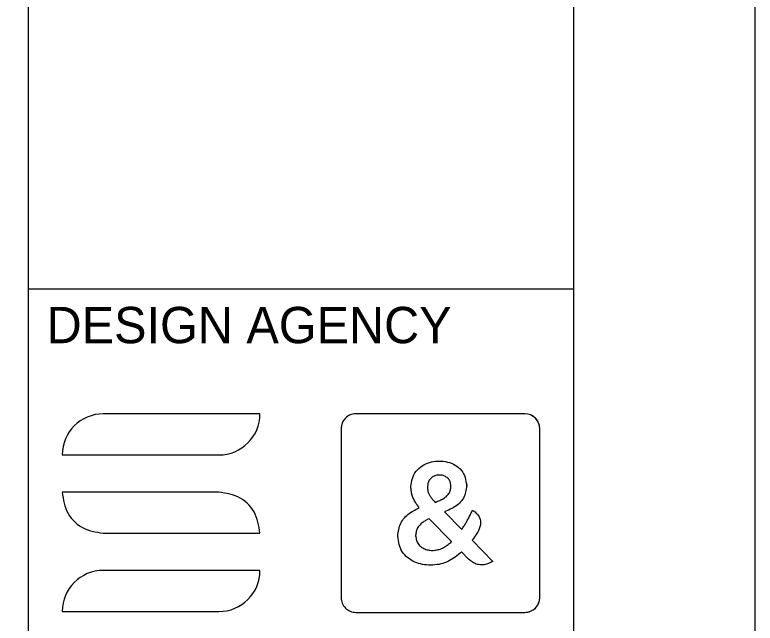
# Model space of a CAD drawing. Extents: x 0 to 34, y 0 to 30.1.
# Drawn here: x 31.963 to 34, y 4.079 to 5.754 of the extents above; entities that cross this region are included whole.
import ezdxf

# ---------------------------------------------------------------- set-up
doc = ezdxf.new("R2010")
doc.units = 0
for name, color, linetype in [('G-BRDR_LOGO', 7, 'Continuous'), ('SH_Border', 7, 'Continuous'), ('SH_Cut_Line', 7, 'Continuous'), ('SH_Data', 7, 'Continuous')]:
    doc.layers.add(name, color=color, linetype=linetype)

msp = doc.modelspace()

# ---------------------------------------------------------------- linework, layer by layer
at = {"layer": 'G-BRDR_LOGO'}
for p, q in [((33.3657, 4.6556), (32.9014, 4.6556)), ((32.8604, 4.6147), (32.8604, 4.1499)), ((33.4071, 4.1505), (33.4071, 4.6147)), ((33.1141, 4.483), (33.112, 4.4817)), ((33.1164, 4.4841), (33.1141, 4.483)), ((33.1187, 4.485), (33.1164, 4.4841)), ((33.1211, 4.4858), (33.1187, 4.485)), ((33.1235, 4.4863), (33.1211, 4.4858)), ((33.126, 4.4867), (33.1235, 4.4863)), ((33.1285, 4.487), (33.126, 4.4867)), ((33.131, 4.487), (33.1285, 4.487)), ((33.1335, 4.487), (33.131, 4.487)), ((33.136, 4.4867), (33.1335, 4.487)), ((33.1385, 4.4863), (33.136, 4.4867)), ((33.1409, 4.4857), (33.1385, 4.4863)), ((33.1433, 4.485), (33.1409, 4.4857)), ((33.1456, 4.484), (33.1433, 4.485)), ((33.1478, 4.4829), (33.1456, 4.484)), ((33.15, 4.4816), (33.1478, 4.4829)), ((33.0996, 4.4636), (33.0991, 4.4612)), ((33.1003, 4.466), (33.0996, 4.4636)), ((33.101, 4.4684), (33.1003, 4.466)), ((33.102, 4.4706), (33.101, 4.4684)), ((33.1032, 4.4728), (33.102, 4.4706)), ((33.1046, 4.4748), (33.1032, 4.4728)), ((33.1062, 4.4768), (33.1046, 4.4748)), ((33.108, 4.4785), (33.1062, 4.4768)), ((33.1099, 4.4802), (33.108, 4.4785)), ((33.112, 4.4817), (33.1099, 4.4802)), ((33.152, 4.48), (33.15, 4.4816)), ((33.1539, 4.4784), (33.152, 4.48)), ((33.1556, 4.4765), (33.1539, 4.4784)), ((33.1571, 4.4746), (33.1556, 4.4765)), ((33.1585, 4.4725), (33.1571, 4.4746)), ((33.1595, 4.4703), (33.1585, 4.4725)), ((33.1604, 4.468), (33.1595, 4.4703)), ((33.1611, 4.4656), (33.1604, 4.468)), ((33.1616, 4.4632), (33.1611, 4.4656)), ((33.1621, 4.4607), (33.1616, 4.4632)), ((33.0984, 4.4562), (33.0981, 4.4537)), ((33.0981, 4.4537), (33.0981, 4.4529)), ((33.0981, 4.4529), (33.0983, 4.4508)), ((33.0983, 4.4508), (33.0985, 4.4488)), ((33.0987, 4.4587), (33.0984, 4.4562)), ((33.0985, 4.4488), (33.0987, 4.4467)), ((33.0991, 4.4612), (33.0987, 4.4587)), ((33.0987, 4.4467), (33.099, 4.4447)), ((33.099, 4.4447), (33.0994, 4.4427)), ((33.0994, 4.4427), (33.0999, 4.4407)), ((33.1595, 4.4409), (33.1604, 4.4436)), ((33.1604, 4.4436), (33.1611, 4.4463)), ((33.1611, 4.4463), (33.1617, 4.4492)), ((33.1617, 4.4492), (33.1623, 4.452)), ((33.1624, 4.4582), (33.1621, 4.4607)), ((33.1623, 4.452), (33.1627, 4.4549)), ((33.1627, 4.4557), (33.1624, 4.4582)), ((33.1627, 4.4549), (33.1627, 4.4557)), ((33.0999, 4.4407), (33.1005, 4.4387)), ((33.1005, 4.4387), (33.1012, 4.4368)), ((33.1012, 4.4368), (33.102, 4.4349)), ((33.102, 4.4349), (33.1029, 4.4331)), ((33.1029, 4.4331), (33.104, 4.4312)), ((33.104, 4.4312), (33.105, 4.4295)), ((33.105, 4.4295), (33.1062, 4.4277)), ((33.1062, 4.4277), (33.1074, 4.426)), ((33.1074, 4.426), (33.1086, 4.4243)), ((33.1086, 4.4243), (33.1098, 4.4227)), ((33.1098, 4.4227), (33.1111, 4.4211)), ((33.1398, 4.421), (33.1422, 4.4225)), ((33.1422, 4.4225), (33.1447, 4.4241)), ((33.1447, 4.4241), (33.1471, 4.4257)), ((33.1471, 4.4257), (33.1494, 4.4275)), ((33.1494, 4.4275), (33.1516, 4.4294)), ((33.1516, 4.4294), (33.1536, 4.4315)), ((33.1536, 4.4315), (33.1554, 4.4336)), ((33.1554, 4.4336), (33.157, 4.4359)), ((33.157, 4.4359), (33.1584, 4.4384)), ((33.1584, 4.4384), (33.1595, 4.4409)), ((33.1111, 4.4211), (33.1124, 4.4195)), ((33.1124, 4.4195), (33.1137, 4.4179)), ((33.1137, 4.4179), (33.1164, 4.4148)), ((33.1164, 4.4148), (33.1191, 4.4117)), ((33.1191, 4.4117), (33.1243, 4.4138)), ((33.1243, 4.4138), (33.127, 4.4149)), ((33.127, 4.4149), (33.1296, 4.416)), ((33.1296, 4.416), (33.1321, 4.4172)), ((33.1321, 4.4172), (33.1347, 4.4184)), ((33.1347, 4.4184), (33.1372, 4.4197)), ((33.1372, 4.4197), (33.1398, 4.421)), ((33.0905, 4.3604), (33.0882, 4.3589)), ((33.0929, 4.3617), (33.0905, 4.3604)), ((33.0952, 4.363), (33.0929, 4.3617)), ((33.0976, 4.3643), (33.0952, 4.363)), ((33.1, 4.3656), (33.0976, 4.3643)), ((33.1024, 4.3668), (33.1, 4.3656)), ((33.1643, 4.3037), (33.1024, 4.3668)), ((33.0711, 4.3416), (33.0698, 4.3392)), ((33.0725, 4.344), (33.0711, 4.3416)), ((33.0741, 4.3462), (33.0725, 4.344)), ((33.0758, 4.3483), (33.0741, 4.3462)), ((33.0776, 4.3504), (33.0758, 4.3483)), ((33.0796, 4.3523), (33.0776, 4.3504)), ((33.0816, 4.3541), (33.0796, 4.3523)), ((33.0838, 4.3558), (33.0816, 4.3541)), ((33.086, 4.3574), (33.0838, 4.3558)), ((33.0882, 4.3589), (33.086, 4.3574)), ((33.0659, 4.3235), (33.0655, 4.3208)), ((33.0655, 4.3208), (33.0655, 4.32)), ((33.0655, 4.32), (33.0661, 4.3168)), ((33.0663, 4.3262), (33.0659, 4.3235)), ((33.0667, 4.3289), (33.0663, 4.3262)), ((33.0673, 4.3316), (33.0667, 4.3289)), ((33.068, 4.3342), (33.0673, 4.3316)), ((33.0688, 4.3367), (33.068, 4.3342)), ((33.0698, 4.3392), (33.0688, 4.3367)), ((33.0661, 4.3168), (33.0666, 4.3137)), ((33.0666, 4.3137), (33.0673, 4.3106)), ((33.0673, 4.3106), (33.068, 4.3076)), ((33.068, 4.3076), (33.069, 4.3047)), ((33.069, 4.3047), (33.0701, 4.3018)), ((33.0701, 4.3018), (33.0716, 4.2991)), ((33.0716, 4.2991), (33.0733, 4.2966)), ((33.1573, 4.2977), (33.1596, 4.2997)), ((33.1596, 4.2997), (33.162, 4.3017)), ((33.162, 4.3017), (33.1643, 4.3037)), ((33.0733, 4.2966), (33.0752, 4.2942)), ((33.0752, 4.2942), (33.0774, 4.292)), ((33.0774, 4.292), (33.0798, 4.2899)), ((33.0798, 4.2899), (33.0824, 4.288)), ((33.0824, 4.288), (33.0851, 4.2864)), ((33.0851, 4.2864), (33.0879, 4.2849)), ((33.0879, 4.2849), (33.0907, 4.2835)), ((33.0907, 4.2835), (33.0937, 4.2824)), ((33.0937, 4.2824), (33.0967, 4.2815)), ((33.0967, 4.2815), (33.0997, 4.2808)), ((33.0997, 4.2808), (33.1028, 4.2802)), ((33.1028, 4.2802), (33.1059, 4.2798)), ((33.1059, 4.2798), (33.109, 4.2796)), ((33.109, 4.2796), (33.1121, 4.2795)), ((33.1121, 4.2795), (33.1152, 4.2796)), ((33.1152, 4.2796), (33.1183, 4.2799)), ((33.1183, 4.2799), (33.1214, 4.2803)), ((33.1214, 4.2803), (33.1244, 4.2809)), ((33.1244, 4.2809), (33.1275, 4.2816)), ((33.1275, 4.2816), (33.1304, 4.2824)), ((33.1304, 4.2824), (33.1334, 4.2834)), ((33.1334, 4.2834), (33.1363, 4.2846)), ((33.1363, 4.2846), (33.1391, 4.2858)), ((33.1391, 4.2858), (33.1419, 4.2872)), ((33.1419, 4.2872), (33.1446, 4.2887)), ((33.1446, 4.2887), (33.1473, 4.2903)), ((33.1473, 4.2903), (33.1499, 4.292)), ((33.1499, 4.292), (33.1524, 4.2939)), ((33.1524, 4.2939), (33.1548, 4.2957)), ((33.1548, 4.2957), (33.1573, 4.2977)), ((32.9014, 4.109), (33.366, 4.109))]:
    msp.add_line(p, q, dxfattribs=at)
for points in [[(32.6372, 4.6556), (32.2061, 4.6556)], [(32.8786, 4.6487), (32.8778, 4.6482), (32.8755, 4.6466), (32.8734, 4.6447), (32.8714, 4.6427), (32.8695, 4.6406), (32.8679, 4.6383), (32.8674, 4.6375)], [(33.366, 4.6556), (32.9014, 4.6556)], [(33.4024, 4.6334), (33.4024, 4.6334), (33.4012, 4.6359), (33.3997, 4.6383), (33.398, 4.6406), (33.3962, 4.6427), (33.3942, 4.6447), (33.392, 4.6466), (33.3898, 4.6482), (33.3874, 4.6497), (33.3866, 4.65)], [(32.8604, 4.6147), (32.8604, 4.1499)], [(33.4071, 4.1499), (33.4071, 4.6147)], [(32.0929, 4.5424), (32.524, 4.5424)], [(33.0884, 4.5151), (33.0934, 4.5176), (33.0986, 4.5198), (33.1039, 4.5216), (33.1093, 4.523), (33.1148, 4.5242), (33.1203, 4.5249), (33.1259, 4.5254), (33.1315, 4.5255), (33.1371, 4.5254), (33.1426, 4.5249), (33.1482, 4.5241), (33.1536, 4.5229), (33.159, 4.5214), (33.1643, 4.5195), (33.1694, 4.5172), (33.1744, 4.5145), (33.1791, 4.5114), (33.1836, 4.5079), (33.1878, 4.5041), (33.1915, 4.4999), (33.1948, 4.4955), (33.1976, 4.4907), (33.1998, 4.4857), (33.2016, 4.4805), (33.203, 4.4752), (33.2041, 4.4697), (33.2051, 4.4641), (33.2061, 4.4581), (33.2054, 4.4532), (33.2048, 4.4488), (33.2041, 4.4444), (33.2032, 4.4401), (33.2021, 4.4358), (33.2008, 4.4317), (33.1992, 4.4277), (33.1973, 4.4238), (33.195, 4.4201), (33.1924, 4.4165), (33.1895, 4.4132), (33.1864, 4.41), (33.1831, 4.4069), (33.1797, 4.4041), (33.1761, 4.4015), (33.1724, 4.3991), (33.1686, 4.3968), (33.1648, 4.3947), (33.1609, 4.3927), (33.1569, 4.3908), (33.1529, 4.389), (33.1489, 4.3872), (33.1449, 4.3855), (33.1925, 4.3371), (33.194, 4.3393), (33.1954, 4.3415), (33.1968, 4.3438), (33.1983, 4.346), (33.1997, 4.3483), (33.2011, 4.3506), (33.2025, 4.3529), (33.2038, 4.3551), (33.2052, 4.3574), (33.2065, 4.3598), (33.2078, 4.3621), (33.2091, 4.3644), (33.2103, 4.3668), (33.2116, 4.3691), (33.2128, 4.3715), (33.214, 4.3739), (33.2152, 4.3763), (33.2164, 4.3786), (33.2176, 4.381), (33.2188, 4.3834), (33.2199, 4.3858), (33.2211, 4.3882), (33.2223, 4.3906), (33.2246, 4.3889), (33.2269, 4.3871), (33.2292, 4.3853), (33.2314, 4.3834), (33.2334, 4.3815), (33.2354, 4.3794), (33.2372, 4.3772), (33.2389, 4.3749), (33.2403, 4.3724), (33.2416, 4.3697), (33.2426, 4.367), (33.2434, 4.3642), (33.244, 4.3613), (33.2444, 4.3585), (33.2445, 4.3556), (33.2443, 4.3527), (33.2439, 4.3499), (33.2433, 4.3471), (33.2426, 4.3444), (33.2417, 4.3416), (33.2407, 4.3389), (33.2397, 4.3362), (33.2386, 4.3335), (33.2379, 4.3323), (33.2368, 4.3305), (33.2354, 4.3283), (33.234, 4.326), (33.2325, 4.3238), (33.2311, 4.3215), (33.2296, 4.3193), (33.2281, 4.317), (33.2266, 4.3149), (33.225, 4.3127), (33.2235, 4.3105), (33.2223, 4.3088), (33.2215, 4.3077), (33.278, 4.2493), (33.2751, 4.2478), (33.2723, 4.2464), (33.2694, 4.245), (33.2665, 4.2437), (33.2636, 4.2425), (33.2606, 4.2415), (33.2576, 4.2407), (33.2545, 4.2401), (33.2513, 4.2397), (33.2482, 4.2395), (33.2449, 4.2396), (33.2418, 4.2399), (33.2386, 4.2404), (33.2355, 4.2411), (33.2325, 4.2421), (33.2295, 4.2433), (33.2267, 4.2446), (33.224, 4.2462), (33.2213, 4.2479), (33.2187, 4.2497), (33.2161, 4.2515), (33.2136, 4.2535), (33.2111, 4.2554), (33.1921, 4.2752), (33.1878, 4.2716), (33.1835, 4.268), (33.1792, 4.2646), (33.1747, 4.2612), (33.1702, 4.258), (33.1655, 4.2551), (33.1606, 4.2523), (33.1556, 4.2498), (33.1505, 4.2476), (33.1453, 4.2456), (33.14, 4.2439), (33.1346, 4.2424), (33.1292, 4.2412), (33.1237, 4.2403), (33.1181, 4.2396), (33.1126, 4.2392), (33.107, 4.2391), (33.1014, 4.2392), (33.0958, 4.2395), (33.0903, 4.2401), (33.0848, 4.241), (33.0793, 4.2422), (33.0739, 4.2437), (33.0685, 4.2455), (33.0633, 4.2476), (33.0582, 4.2501), (33.0532, 4.2528), (33.0484, 4.2559), (33.0438, 4.2593), (33.0395, 4.263), (33.0355, 4.267), (33.0319, 4.2712), (33.0288, 4.2757), (33.0261, 4.2805), (33.0239, 4.2855), (33.0221, 4.2907), (33.0205, 4.296), (33.0193, 4.3015), (33.0182, 4.3071), (33.0172, 4.3127), (33.0163, 4.3187), (33.0169, 4.3238), (33.0174, 4.3283), (33.0181, 4.3328), (33.0189, 4.3372), (33.0199, 4.3416), (33.0211, 4.3459), (33.0226, 4.3501), (33.0244, 4.3542), (33.0265, 4.3582), (33.029, 4.362), (33.0317, 4.3657), (33.0346, 4.3692), (33.0377, 4.3725), (33.041, 4.3756), (33.0445, 4.3786), (33.0481, 4.3813), (33.0518, 4.3839), (33.0556, 4.3863), (33.0595, 4.3886), (33.0634, 4.3908), (33.0674, 4.3929), (33.0714, 4.3949), (33.0755, 4.397), (33.0738, 4.3992), (33.0722, 4.4014), (33.0706, 4.4037), (33.069, 4.406), (33.0675, 4.4082), (33.066, 4.4106), (33.0645, 4.4129), (33.0631, 4.4153), (33.0618, 4.4177), (33.0605, 4.4202), (33.0593, 4.4227), (33.0582, 4.4252), (33.0572, 4.4278), (33.0563, 4.4304), (33.0555, 4.4331), (33.0548, 4.4357), (33.0542, 4.4384), (33.0538, 4.4411), (33.0534, 4.4439), (33.0531, 4.4466), (33.0529, 4.4494), (33.0526, 4.4521), (33.0524, 4.4554), (33.0534, 4.4613), (33.0543, 4.4669), (33.0555, 4.4724), (33.0569, 4.4778), (33.0587, 4.483), (33.0608, 4.488), (33.0635, 4.4928), (33.0667, 4.4973), (33.0704, 4.5015), (33.0744, 4.5054), (33.0788, 4.509), (33.0835, 4.5122), (33.0884, 4.5151)], [(32.6168, 4.3923), (32.6122, 4.3986), (32.6072, 4.4045), (32.6017, 4.41), (32.5957, 4.4151), (32.5895, 4.4196), (32.5829, 4.4237), (32.5761, 4.4271), (32.569, 4.43), (32.5618, 4.4324), (32.5545, 4.4344), (32.547, 4.4361), (32.5394, 4.4375), (32.5317, 4.4388), (32.524, 4.44), (32.0929, 4.44), (32.0941, 4.4324), (32.0954, 4.4247), (32.0968, 4.4171), (32.0985, 4.4096), (32.1006, 4.4023), (32.103, 4.395), (32.1058, 4.388), (32.1093, 4.3812), (32.1133, 4.3746), (32.1179, 4.3684), (32.1229, 4.3624), (32.1284, 4.3569), (32.1344, 4.3518), (32.1406, 4.3473), (32.1472, 4.3433), (32.154, 4.3398), (32.1611, 4.3369), (32.1683, 4.3345), (32.1756, 4.3325), (32.1831, 4.3308), (32.1907, 4.3294), (32.1984, 4.3281), (32.2061, 4.3269), (32.6372, 4.3269), (32.636, 4.3345), (32.6347, 4.3422), (32.6333, 4.3498), (32.6316, 4.3573), (32.6296, 4.3646), (32.6271, 4.3719), (32.6243, 4.3789), (32.6208, 4.3857), (32.6168, 4.3923)], [(32.6372, 4.2245), (32.2061, 4.2245)], [(32.0929, 4.1113), (32.524, 4.1113)], [(32.9014, 4.109), (33.366, 4.109)]]:
    msp.add_lwpolyline(points, dxfattribs=at)
for points in [[(33.1921, 4.2752), (33.1878, 4.2716), (33.1835, 4.268), (33.1792, 4.2646), (33.1747, 4.2612), (33.1702, 4.258), (33.1655, 4.2551), (33.1606, 4.2523), (33.1556, 4.2498), (33.1505, 4.2476), (33.1453, 4.2456), (33.14, 4.2439), (33.1346, 4.2424), (33.1292, 4.2412), (33.1237, 4.2403), (33.1181, 4.2396), (33.1126, 4.2392), (33.107, 4.2391), (33.1014, 4.2392), (33.0958, 4.2395), (33.0903, 4.2401), (33.0848, 4.241), (33.0793, 4.2422), (33.0739, 4.2437), (33.0685, 4.2455), (33.0633, 4.2476), (33.0582, 4.2501), (33.0532, 4.2528), (33.0484, 4.2559), (33.0438, 4.2593), (33.0395, 4.263), (33.0355, 4.267), (33.0319, 4.2712), (33.0288, 4.2757), (33.0261, 4.2805), (33.0239, 4.2855), (33.0221, 4.2907), (33.0205, 4.296), (33.0193, 4.3015), (33.0182, 4.3071), (33.0172, 4.3127), (33.0163, 4.3184), (33.0163, 4.3192), (33.0169, 4.3238), (33.0174, 4.3283), (33.0181, 4.3328), (33.0189, 4.3372), (33.0199, 4.3416), (33.0211, 4.3459), (33.0226, 4.3501), (33.0244, 4.3542), (33.0265, 4.3582), (33.029, 4.362), (33.0317, 4.3657), (33.0346, 4.3692), (33.0377, 4.3725), (33.041, 4.3756), (33.0445, 4.3786), (33.0481, 4.3813), (33.0518, 4.3839), (33.0556, 4.3863), (33.0595, 4.3886), (33.0634, 4.3908), (33.0674, 4.3929), (33.0714, 4.3949), (33.0755, 4.397), (33.0738, 4.3992), (33.0722, 4.4014), (33.0706, 4.4037), (33.069, 4.406), (33.0675, 4.4082), (33.066, 4.4106), (33.0645, 4.4129), (33.0631, 4.4153), (33.0618, 4.4177), (33.0605, 4.4202), (33.0593, 4.4227), (33.0582, 4.4252), (33.0572, 4.4278), (33.0563, 4.4304), (33.0555, 4.4331), (33.0548, 4.4357), (33.0542, 4.4384), (33.0538, 4.4411), (33.0534, 4.4439), (33.0531, 4.4466), (33.0529, 4.4494), (33.0526, 4.4521), (33.0524, 4.4549), (33.0524, 4.4557), (33.0534, 4.4613), (33.0543, 4.4669), (33.0555, 4.4724), (33.0569, 4.4778), (33.0587, 4.483), (33.0608, 4.488), (33.0635, 4.4928), (33.0667, 4.4973), (33.0704, 4.5015), (33.0744, 4.5054), (33.0788, 4.509), (33.0835, 4.5122), (33.0884, 4.5151), (33.0934, 4.5176), (33.0986, 4.5198), (33.1039, 4.5216), (33.1093, 4.523), (33.1148, 4.5242), (33.1203, 4.5249), (33.1259, 4.5254), (33.1315, 4.5255), (33.1371, 4.5254), (33.1426, 4.5249), (33.1482, 4.5241), (33.1536, 4.5229), (33.159, 4.5214), (33.1643, 4.5195), (33.1694, 4.5172), (33.1744, 4.5145), (33.1791, 4.5114), (33.1836, 4.5079), (33.1878, 4.5041), (33.1915, 4.4999), (33.1948, 4.4955), (33.1976, 4.4907), (33.1998, 4.4857), (33.2016, 4.4805), (33.203, 4.4752), (33.2041, 4.4697), (33.2051, 4.4641), (33.206, 4.4585), (33.206, 4.4577), (33.2054, 4.4532), (33.2048, 4.4488), (33.2041, 4.4444), (33.2032, 4.4401), (33.2021, 4.4358), (33.2008, 4.4317), (33.1992, 4.4277), (33.1973, 4.4238), (33.195, 4.4201), (33.1924, 4.4165), (33.1895, 4.4132), (33.1864, 4.41), (33.1831, 4.4069), (33.1797, 4.4041), (33.1761, 4.4015), (33.1724, 4.3991), (33.1686, 4.3968), (33.1648, 4.3947), (33.1609, 4.3927), (33.1569, 4.3908), (33.1529, 4.389), (33.1489, 4.3872), (33.1449, 4.3855), (33.1925, 4.3371), (33.194, 4.3393), (33.1954, 4.3415), (33.1968, 4.3438), (33.1983, 4.346), (33.1997, 4.3483), (33.2011, 4.3506), (33.2025, 4.3529), (33.2038, 4.3551), (33.2052, 4.3574), (33.2065, 4.3598), (33.2078, 4.3621), (33.2091, 4.3644), (33.2103, 4.3668), (33.2116, 4.3691), (33.2128, 4.3715), (33.214, 4.3739), (33.2152, 4.3763), (33.2164, 4.3786), (33.2176, 4.381), (33.2188, 4.3834), (33.2199, 4.3858), (33.2211, 4.3882), (33.2223, 4.3906), (33.2246, 4.3889), (33.2269, 4.3871), (33.2292, 4.3853), (33.2314, 4.3834), (33.2334, 4.3815), (33.2354, 4.3794), (33.2372, 4.3772), (33.2389, 4.3749), (33.2403, 4.3724), (33.2416, 4.3697), (33.2426, 4.367), (33.2434, 4.3642), (33.244, 4.3613), (33.2444, 4.3585), (33.2445, 4.3556), (33.2443, 4.3527), (33.2439, 4.3499), (33.2433, 4.3471), (33.2426, 4.3444), (33.2417, 4.3416), (33.2407, 4.3389), (33.2397, 4.3362), (33.2386, 4.3335), (33.2379, 4.3323), (33.2372, 4.3312), (33.2365, 4.33), (33.2358, 4.3289), (33.2351, 4.3278), (33.2343, 4.3266), (33.2336, 4.3255), (33.2329, 4.3243), (33.2322, 4.3232), (33.2314, 4.3221), (33.2307, 4.321), (33.23, 4.3198), (33.2292, 4.3187), (33.2285, 4.3176), (33.2277, 4.3165), (33.2269, 4.3154), (33.2262, 4.3143), (33.2254, 4.3132), (33.2246, 4.3121), (33.2238, 4.311), (33.2231, 4.3099), (33.2223, 4.3088), (33.2215, 4.3077), (33.278, 4.2493), (33.2751, 4.2478), (33.2723, 4.2464), (33.2694, 4.245), (33.2665, 4.2437), (33.2636, 4.2425), (33.2606, 4.2415), (33.2576, 4.2407), (33.2545, 4.2401), (33.2513, 4.2397), (33.2482, 4.2395), (33.2449, 4.2396), (33.2418, 4.2399), (33.2386, 4.2404), (33.2355, 4.2411), (33.2325, 4.2421), (33.2295, 4.2433), (33.2267, 4.2446), (33.224, 4.2462), (33.2213, 4.2479), (33.2187, 4.2497), (33.2161, 4.2515), (33.2136, 4.2535), (33.2111, 4.2554)], [(33.1627, 4.4557), (33.1624, 4.4582), (33.1621, 4.4607), (33.1616, 4.4632), (33.1611, 4.4656), (33.1604, 4.468), (33.1595, 4.4703), (33.1585, 4.4725), (33.1571, 4.4746), (33.1556, 4.4765), (33.1539, 4.4784), (33.152, 4.48), (33.15, 4.4816), (33.1478, 4.4829), (33.1456, 4.484), (33.1433, 4.485), (33.1409, 4.4857), (33.1385, 4.4863), (33.136, 4.4867), (33.1335, 4.487), (33.131, 4.487), (33.1285, 4.487), (33.126, 4.4867), (33.1235, 4.4863), (33.1211, 4.4858), (33.1187, 4.485), (33.1164, 4.4841), (33.1141, 4.483), (33.112, 4.4817), (33.1099, 4.4802), (33.108, 4.4785), (33.1062, 4.4768), (33.1046, 4.4748), (33.1032, 4.4728), (33.102, 4.4706), (33.101, 4.4684), (33.1003, 4.466), (33.0996, 4.4636), (33.0991, 4.4612), (33.0987, 4.4587), (33.0984, 4.4562), (33.0981, 4.4537), (33.0981, 4.4529), (33.0983, 4.4508), (33.0985, 4.4488), (33.0987, 4.4467), (33.099, 4.4447), (33.0994, 4.4427), (33.0999, 4.4407), (33.1005, 4.4387), (33.1012, 4.4368), (33.102, 4.4349), (33.1029, 4.4331), (33.104, 4.4312), (33.105, 4.4295), (33.1062, 4.4277), (33.1074, 4.426), (33.1086, 4.4243), (33.1098, 4.4227), (33.1111, 4.4211), (33.1124, 4.4195), (33.1137, 4.4179), (33.1164, 4.4148), (33.1191, 4.4117), (33.1243, 4.4138), (33.127, 4.4149), (33.1296, 4.416), (33.1321, 4.4172), (33.1347, 4.4184), (33.1372, 4.4197), (33.1398, 4.421), (33.1422, 4.4225), (33.1447, 4.4241), (33.1471, 4.4257), (33.1494, 4.4275), (33.1516, 4.4294), (33.1536, 4.4315), (33.1554, 4.4336), (33.157, 4.4359), (33.1584, 4.4384), (33.1595, 4.4409), (33.1604, 4.4436), (33.1611, 4.4463), (33.1617, 4.4492), (33.1623, 4.452), (33.1627, 4.4549)], [(33.0655, 4.32), (33.0661, 4.3168), (33.0666, 4.3137), (33.0673, 4.3106), (33.068, 4.3076), (33.069, 4.3047), (33.0701, 4.3018), (33.0716, 4.2991), (33.0733, 4.2966), (33.0752, 4.2942), (33.0774, 4.292), (33.0798, 4.2899), (33.0824, 4.288), (33.0851, 4.2864), (33.0879, 4.2849), (33.0907, 4.2835), (33.0937, 4.2824), (33.0967, 4.2815), (33.0997, 4.2808), (33.1028, 4.2802), (33.1059, 4.2798), (33.109, 4.2796), (33.1121, 4.2795), (33.1152, 4.2796), (33.1183, 4.2799), (33.1214, 4.2803), (33.1244, 4.2809), (33.1275, 4.2816), (33.1304, 4.2824), (33.1334, 4.2834), (33.1363, 4.2846), (33.1391, 4.2858), (33.1419, 4.2872), (33.1446, 4.2887), (33.1473, 4.2903), (33.1499, 4.292), (33.1524, 4.2939), (33.1548, 4.2957), (33.1573, 4.2977), (33.1596, 4.2997), (33.162, 4.3017), (33.1643, 4.3037), (33.1024, 4.3668), (33.1, 4.3656), (33.0976, 4.3643), (33.0952, 4.363), (33.0929, 4.3617), (33.0905, 4.3604), (33.0882, 4.3589), (33.086, 4.3574), (33.0838, 4.3558), (33.0816, 4.3541), (33.0796, 4.3523), (33.0776, 4.3504), (33.0758, 4.3483), (33.0741, 4.3462), (33.0725, 4.344), (33.0711, 4.3416), (33.0698, 4.3392), (33.0688, 4.3367), (33.068, 4.3342), (33.0673, 4.3316), (33.0667, 4.3289), (33.0663, 4.3262), (33.0659, 4.3235), (33.0655, 4.3208)]]:
    msp.add_lwpolyline(points, close=True, dxfattribs=at)
for centre, radius, start, end in [((32.2061, 4.5424), 0.1132, 90, 180), ((32.524, 4.6556), 0.1132, 270, 360), ((32.9014, 4.6147), 0.041, 90.0057, 180), ((32.9014, 4.6147), 0.041, 89.9943, 180), ((33.3659, 4.6144), 0.0413, 0.4198, 90.1682), ((33.3659, 4.6144), 0.0413, 0.4198, 89.8318), ((32.2061, 4.1113), 0.1132, 90, 180), ((32.524, 4.2245), 0.1132, 270, 360), ((32.9014, 4.1499), 0.041, 180, 270.0057), ((32.9014, 4.1499), 0.041, 180, 270.0057), ((33.3659, 4.1502), 0.0413, 270.1682, 0.4198), ((33.3659, 4.1502), 0.0413, 270.1682, 359.5802)]:
    msp.add_arc(centre, radius, start, end, dxfattribs=at)
at = {"layer": 'SH_Border'}
for p, q in [((32, 0.5), (32, 21.5)), ((32, 5), (33.5, 5))]:
    msp.add_line(p, q, dxfattribs=at)
msp.add_lwpolyline([(1.5, 21.5), (33.5, 21.5), (33.5, 0.5), (1.5, 0.5)], close=True, dxfattribs=at)
at = {"layer": 'SH_Cut_Line'}
msp.add_lwpolyline([(0, 0), (34, 0), (34, 22), (0, 22)], close=True, dxfattribs=at)

# ---------------------------------------------------------------- texts
at = {"layer": 'SH_Data'}
msp.add_text('DESIGN AGENCY', height=0.1, dxfattribs=at).set_placement((32.05, 4.85))

doc.saveas('drawing.dxf')
